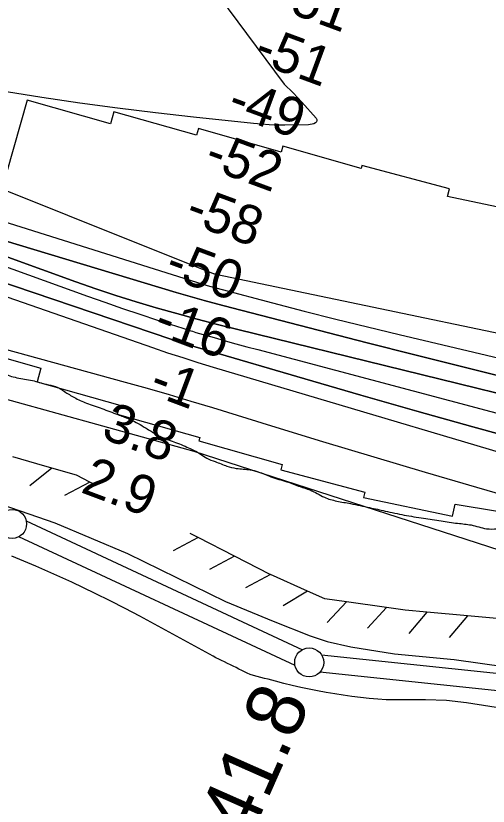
# Model space of a CAD drawing. Extents: x 3855477 to 3893699, y 299188 to 325115.
# Drawn here: x 3867708 to 3868521, y 310145 to 311507 of the extents above; entities that cross this region are included whole.
import ezdxf

# ---------------------------------------------------------------- set-up
doc = ezdxf.new("R2010")
doc.units = 0
for name, color, linetype in [('V-LEVE-TOET', 7, 'Continuous'), ('V-RIVR-EDGE', 7, 'Continuous'), ('V-RIVR-RANG', 7, 'Continuous'), ('V-RRAP-FSHR', 7, 'Continuous'), ('V-RRAP-RVMT', 7, 'Continuous'), ('V-SURV-IDEN', 7, 'Continuous'), ('V-SURV-LINE', 7, 'Continuous'), ('V-TOPO-DPTH', 7, 'Continuous'), ('V-TOPO-MAJR', 7, 'Continuous'), ('V-TOPO-MINR', 7, 'Continuous'), ('V-TOPO-WATR', 7, 'Continuous')]:
    doc.layers.add(name, color=color, linetype=linetype)

msp = doc.modelspace()

# ---------------------------------------------------------------- linework, layer by layer
at = {"layer": 'V-LEVE-TOET'}
for points in [[(3865781.2, 311251.3), (3865918.8, 311165.7), (3865932.5, 311157.1), (3865959.4, 311144.2), (3866026.4, 311126.1), (3866170, 311093.2), (3866361.4, 311047.3), (3866522.9, 311004.6), (3866745.5, 310954.1), (3866852, 310925.9), (3867039.2, 310870.9), (3867258, 310807.2), (3867465.4, 310737.1), (3867653.1, 310675), (3867775, 310633.4), (3867899.8, 310580.3), (3868068.6, 310497.4), (3868151, 310463.5), (3868214.9, 310438.2), (3868244.2, 310428.8), (3868284.9, 310419.4), (3868359.8, 310407.7)], [(3868345.9, 310328.1), (3868331.1, 310329.2), (3868316.2, 310330.6), (3868301.4, 310332.2), (3868286.5, 310334), (3868271.8, 310336), (3868257, 310338.3), (3868242.3, 310340.8), (3868227.6, 310343.5), (3868213, 310346.4), (3868198.4, 310349.5), (3868183.8, 310352.9), (3868169.4, 310356.5), (3868154.9, 310360.3), (3868148.6, 310361.9), (3868142.2, 310363.6), (3868135.9, 310365.2), (3868129.6, 310366.9), (3868123.4, 310368.6), (3868117.2, 310370.2), (3868111.1, 310371.9), (3868106.4, 310374.1), (3868101.7, 310376.5), (3868096.9, 310378.8), (3868092, 310381.2), (3868087.1, 310383.6), (3868082.2, 310386), (3868077.2, 310388.5), (3868072.2, 310390.9), (3868067.2, 310393.4), (3868062.2, 310395.8), (3868057.2, 310398.3), (3868052.2, 310400.7), (3868047.3, 310403.2), (3868022.2, 310417.3), (3867997.1, 310431.2), (3867971.9, 310445), (3867946.5, 310458.7), (3867921.2, 310472.2), (3867895.7, 310485.5), (3867870.1, 310498.7), (3867844.5, 310511.7), (3867824.2, 310521.4), (3867803.8, 310530.9), (3867783.3, 310540.3), (3867762.7, 310549.4), (3867742, 310558.4), (3867721.2, 310567.1), (3867700.4, 310575.6)], [(3868359.8, 310407.7), (3868462.9, 310397.5), (3868552.6, 310385)], [(3868553.6, 310311.9), (3868484, 310322.7), (3868449.5, 310327.2), (3868413.4, 310328), (3868381.8, 310327.9), (3868345.9, 310328.1)]]:
    msp.add_lwpolyline(points, dxfattribs=at)
at = {"layer": 'V-RIVR-EDGE'}
msp.add_spline([(3863207.1, 312832.2), (3863229.9, 312820.5), (3863243.5, 312811.8), (3863252.2, 312800.6), (3863256, 312790.4), (3863258, 312782.1), (3863257.5, 312769.5), (3863258.4, 312767), (3863259.9, 312761.2), (3863272.5, 312752), (3863294.8, 312738.3), (3863304.9, 312730.5), (3863319.5, 312720.3), (3863340.8, 312706.1), (3863352, 312701.7), (3863367, 312691), (3863378.2, 312682.7), (3863401.9, 312671), (3863427.1, 312656.4), (3863482.4, 312619.3), (3863528.5, 312589.1), (3863577.5, 312559.9), (3863604.1, 312542.3), (3863636.6, 312517.5), (3863649.7, 312508.2), (3863660.4, 312503.8), (3863682.7, 312489.7), (3863711.3, 312471.6), (3863738.9, 312455.5), (3863758.3, 312443.8), (3863780.1, 312431.2), (3863800.5, 312415.1), (3863817, 312406.8), (3863839.8, 312392.2), (3863862.1, 312377.5), (3863889.7, 312359), (3863936.7, 312330.2), (3863968.7, 312306.9), (3863983.8, 312297.1), (3864001.7, 312287.3), (3864027.4, 312273.7), (3864050.2, 312262.5), (3864086.1, 312242.9), (3864114.2, 312230.7), (3864161.8, 312206.8), (3864218.5, 312183.4), (3864252, 312168.7), (3864285.9, 312149.2), (3864306.8, 312137.5), (3864333.5, 312126.3), (3864359.7, 312113.6), (3864405.3, 312090.6), (3864433.4, 312079.9), (3864480.5, 312059.9), (3864519.8, 312042.8), (3864559.5, 312026.6), (3864597.4, 312010), (3864673.5, 311974.9), (3864716.2, 311957.3), (3864748.2, 311942.6), (3864782.2, 311928.5), (3864814.7, 311917.2), (3864837.5, 311908.4), (3864857.4, 311899.1), (3864871, 311891.8), (3864889.4, 311885.5), (3864901.6, 311881.1), (3864917.6, 311873.7), (3864943.3, 311864), (3864968, 311853.2), (3864991.3, 311844.4), (3865007.8, 311838.6), (3865027.2, 311829.8), (3865055.8, 311817.6), (3865074.3, 311810.2), (3865099.5, 311798), (3865169.3, 311767.3), (3865206.7, 311751.1), (3865252.8, 311727.2), (3865287.7, 311710.6), (3865320.2, 311696.5), (3865350.8, 311682.8), (3865409.5, 311654), (3865441.5, 311635.9), (3865468.1, 311618.4), (3865502.5, 311593.5), (3865519, 311581.9), (3865540.8, 311565.8), (3865562.2, 311550.7), (3865593.2, 311530.7), (3865614.5, 311512.7), (3865636.3, 311497.1), (3865660.6, 311479.5), (3865674.1, 311466.9), (3865694.5, 311450.8), (3865723.6, 311431.3), (3865765.8, 311405.4), (3865794.9, 311386.9), (3865822.5, 311368.4), (3865843.8, 311357.2), (3865860.8, 311347.4), (3865894.8, 311332.3), (3865922.9, 311321), (3865957.4, 311306.9), (3865987, 311294.2), (3866029.2, 311278), (3866067, 311265.3), (3866101.5, 311251.6), (3866129.6, 311241.9), (3866147.6, 311237.9), (3866169.4, 311232), (3866197.5, 311224.2), (3866231, 311213), (3866265.5, 311203.2), (3866285.9, 311197.3), (3866332, 311184.1), (3866359.1, 311172.8), (3866381, 311168.4), (3866393.6, 311165.9), (3866400.9, 311160.6), (3866406.7, 311158.6), (3866430.5, 311150.3), (3866466.4, 311139), (3866495.5, 311132.2), (3866529, 311121.9), (3866564.4, 311113.1), (3866587.2, 311105.7), (3866615.8, 311098.8), (3866658.1, 311087.1), (3866694.5, 311075.3), (3866714.4, 311068.5), (3866741.5, 311059.2), (3866767.3, 311055.7), (3866784.7, 311052.3), (3866816.3, 311042), (3866834.7, 311036.1), (3866869.2, 311024.4), (3866903.1, 311013.2), (3866908.5, 311009.3), (3866908.9, 311004.4), (3866908.9, 311002.5), (3866903.6, 311000.5), (3866900.2, 310996.6), (3866897.7, 310988.9), (3866897.7, 310988.4), (3866901.6, 310984.5), (3866906.9, 310981.1), (3866918.6, 310978.1), (3866929.8, 310976.2), (3866933.6, 310977.1), (3866939.5, 310985.4), (3866939, 310987.8), (3866937.6, 310989.8), (3866932.7, 310990.7), (3866924, 310991.7), (3866922.5, 310993.7), (3866920.6, 310999), (3866921.1, 311001.9), (3866924, 311002.9), (3866927.4, 311002.9), (3866930.8, 311002.9), (3866947.3, 310999.9), (3866980.3, 310990.6), (3867010.4, 310980.3), (3867026.4, 310974.5), (3867063.3, 310966.1), (3867093.4, 310953.4), (3867109.4, 310952.9), (3867128.8, 310946.1), (3867179.7, 310930.9), (3867221.5, 310918.2), (3867256.9, 310905.4), (3867293.3, 310893.2), (3867338.4, 310880), (3867370, 310870.7), (3867412.2, 310857.9), (3867470.9, 310839.3), (3867485.9, 310835.4), (3867499.1, 310836.9), (3867515.1, 310844.6), (3867537, 310860.6), (3867550.6, 310874.1), (3867558.4, 310888.7), (3867566.2, 310900.8), (3867575, 310909.5), (3867591, 310918.7), (3867596.9, 310919.2), (3867603.7, 310919.1), (3867628.4, 310912.3), (3867660.9, 310901), (3867685.2, 310890.8), (3867709.4, 310883.4), (3867736.1, 310878.5), (3867759.9, 310872.1), (3867775.9, 310868.2), (3867791.5, 310859.4), (3867808.4, 310849.2), (3867829.3, 310839.4), (3867856, 310830.1), (3867883.1, 310819.9), (3867902.1, 310812.5), (3867927.8, 310798.9), (3867944.7, 310788.6), (3867961.2, 310779.9), (3867986, 310770.6), (3867999.1, 310765.2), (3868011.2, 310759.8), (3868025.8, 310751.5), (3868036.4, 310744.7), (3868051, 310738.8), (3868071.4, 310731), (3868087.4, 310727.1), (3868111.6, 310724.6), (3868125.2, 310721.2), (3868147.1, 310712.4), (3868174.7, 310704.1), (3868197.5, 310695.7), (3868214.5, 310689.9), (3868239.3, 310677.2), (3868260.6, 310670.8), (3868284.4, 310666.4), (3868316.9, 310659.5), (3868344.1, 310653.6), (3868376.6, 310646.7), (3868410.1, 310641.3), (3868440.2, 310636.9), (3868468.8, 310632.4), (3868492.1, 310629.5), (3868518.4, 310623.1), (3868536.8, 310623), (3868547.5, 310623.5), (3868562.5, 310620.5), (3868581, 310615.2), (3868596.5, 310614.1), (3868609.1, 310608.8), (3868621.3, 310608.7), (3868632.9, 310606.8), (3868646, 310603.3), (3868659.6, 310598.9), (3868680.5, 310591.6), (3868698, 310586.7), (3868708.2, 310587.6), (3868719.3, 310587.6), (3868733.4, 310585.6), (3868758.2, 310579.8), (3868781.4, 310573.9), (3868804.7, 310569.9), (3868819.8, 310566), (3868824.2, 310566), (3868832.9, 310567.9), (3868838.7, 310567.9), (3868853.8, 310568.3), (3868866.9, 310566.4), (3868878.1, 310563.9), (3868891.7, 310564.4), (3868904.3, 310564.3), (3868919.8, 310562.8), (3868941.2, 310556.5), (3868965.4, 310550.6), (3869003.8, 310543.7), (3869038.3, 310539.7), (3869049.9, 310537.8), (3869068.4, 310532.4), (3869091.7, 310530.8), (3869110.6, 310529.3), (3869128.6, 310526.4), (3869142.1, 310518.6), (3869157.6, 310506.9), (3869177, 310489.8), (3869190.1, 310479.1), (3869202.2, 310469.9), (3869217.3, 310463), (3869243, 310454.7), (3869275, 310445.9), (3869293, 310441.5), (3869305.6, 310442.4), (3869320.7, 310438.5), (3869355.6, 310430.6), (3869392, 310421.3), (3869425, 310412.5), (3869458.5, 310398.8), (3869488.1, 310385.1), (3869524.9, 310367.1), (3869556, 310352), (3869578.3, 310338.8), (3869601.6, 310328.5), (3869624.4, 310322.2), (3869655.9, 310315.8), (3869691.4, 310308.9), (3869727.8, 310299.6), (3869752.5, 310295.1), (3869779.2, 310289.7), (3869816.1, 310283.3), (3869843.8, 310279.4), (3869864.6, 310274.5), (3869888.9, 310264.7), (3869906.4, 310256.9), (3869925.8, 310252.5), (3869942.3, 310244.6), (3869966, 310233.4), (3869989.3, 310228), (3870019.4, 310219.2), (3870039.3, 310217.2), (3870097.6, 310207.4), (3870123.3, 310204.9), (3870164.6, 310196.5), (3870192.7, 310192.1), (3870226.7, 310187.6), (3870265.1, 310185.1), (3870295.7, 310184), (3870321.9, 310184.9), (3870353.5, 310186.3), (3870391.3, 310183.8), (3870439.4, 310181.3), (3870483.6, 310179.7), (3870533.1, 310177.1), (3870576.3, 310177.5), (3870606, 310177.9), (3870635.1, 310178.3), (3870679.8, 310176.3), (3870709.4, 310177.7), (3870754.6, 310180), (3870836.7, 310190), (3870888.2, 310191.3), (3870912.4, 310192.7), (3870946.4, 310195.1), (3870977.5, 310199.4), (3871022.2, 310209.4), (3871049.9, 310218.6), (3871070.8, 310224.9), (3871091.7, 310224.8), (3871110.7, 310223.8), (3871127.6, 310219.9), (3871149.5, 310210.1), (3871180, 310195.9), (3871198.5, 310187.6), (3871229.5, 310178.8), (3871247, 310177.3), (3871265.9, 310176.3), (3871287.8, 310173.3), (3871310.6, 310170.8), (3871328.6, 310167.4), (3871341.2, 310165.9), (3871353.8, 310165.4), (3871367.9, 310169.3), (3871397.5, 310176), (3871415, 310178.4), (3871443.7, 310181.7), (3871467, 310183.6), (3871496.6, 310185.9), (3871534, 310188.8), (3871547.6, 310190.7), (3871571.9, 310194.5), (3871607.9, 310199.7), (3871648.2, 310206.4), (3871686.1, 310215.1), (3871735.2, 310226.1), (3871771.6, 310234.8), (3871791.1, 310234.7), (3871801.3, 310238.6), (3871824.1, 310243.4), (3871860.5, 310252), (3871894.5, 310256.3), (3871929, 310257.7), (3871967.4, 310258.6), (3872001.4, 310258), (3872037.8, 310257), (3872067.4, 310255.4), (3872101.9, 310257.8), (3872150, 310258.6), (3872177.2, 310260.5), (3872227.2, 310270.6), (3872274.4, 310278.2), (3872295.7, 310280.1), (3872312.2, 310280.1), (3872321.5, 310280), (3872332.6, 310280.5), (3872352.1, 310286.3), (3872373, 310287.2), (3872406, 310287.6), (3872422, 310288.5), (3872452.6, 310292.3), (3872488.1, 310300), (3872537.2, 310311.6), (3872583.8, 310317.8), (3872632.9, 310322.5), (3872668.8, 310329.2), (3872731, 310339.7), (3872796.1, 310351.2), (3872849.1, 310364.2), (3872896.2, 310376.7), (3872941.9, 310393.6), (3872970.6, 310407.6), (3873015.3, 310426.4), (3873066.4, 310453), (3873096, 310468.5), (3873134, 310485.4), (3873164.6, 310501.8), (3873227.8, 310533.7), (3873273, 310558.4), (3873325.6, 310585.9), (3873391.7, 310620.7), (3873435.5, 310646.9), (3873471, 310665.2), (3873502.1, 310685.1), (3873530.8, 310699.6), (3873577.9, 310719.4), (3873620.7, 310740.6), (3873650.9, 310754.6), (3873683.4, 310774.5), (3873708.3, 310795.3), (3873753, 310827.2), (3873787.6, 310858.2), (3873822.1, 310892.6), (3873850.4, 310914.4), (3873872.2, 310928.4), (3873893.7, 310947.3), (3873917, 310966.2), (3873944.3, 310988.9), (3873975.4, 311014.6), (3874011.4, 311043.2), (3874039.2, 311069.3), (3874068.9, 311102.8), (3874103, 311145.4), (3874137.6, 311188.1), (3874145.8, 311194.8), (3874157.5, 311200.2), (3874165.3, 311200.6), (3874172.6, 311200.1), (3874181.3, 311186.5), (3874183.2, 311173.9)], degree=3, dxfattribs=at)
at = {"layer": 'V-RRAP-FSHR'}
for p, q in [((3867769.5, 310727.6), (3867731.4, 310697.1)), ((3867834.9, 310703.4), (3867791.7, 310680.6)), ((3868021.8, 310607.7), (3867978.7, 310584.9)), ((3868084.1, 310575.8), (3868041, 310553)), ((3868146.4, 310543.9), (3868103.3, 310521)), ((3868210.3, 310515.3), (3868168.4, 310490.3)), ((3868277.2, 310497), (3868243.9, 310461.2)), ((3868346.5, 310487.4), (3868313.3, 310451.6)), ((3868416, 310479.5), (3868384.5, 310442.2)), ((3868485.7, 310473), (3868454.2, 310435.8))]:
    msp.add_line(p, q, dxfattribs=at)
for points in [[(3865854.4, 311447), (3867462.7, 310909.5), (3868014.1, 310756.9), (3868561.3, 310579.9), (3868891.6, 310484.2), (3869212, 310426.8), (3869707.5, 310257), (3870239.9, 310178.1), (3870574.8, 310145.5), (3871160.4, 310198.8), (3872092.5, 310231.3)], [(3867769.5, 310727.6), (3867743.9, 310735.1), (3867702.2, 310746.7)], [(3867834.9, 310703.4), (3867812.2, 310715.1), (3867769.5, 310727.6)], [(3867846.3, 310697.6), (3867834.9, 310703.4)], [(3868021.8, 310607.7), (3868008, 310614.8)], [(3868084.1, 310575.8), (3868021.8, 310607.7)], [(3868146.4, 310543.9), (3868145.7, 310544.2), (3868084.1, 310575.8)], [(3868277.2, 310497), (3868239.9, 310502.1), (3868210.3, 310515.3), (3868146.4, 310543.9)], [(3868346.5, 310487.4), (3868277.2, 310497)], [(3868416, 310479.5), (3868378.5, 310482.9), (3868346.5, 310487.4)], [(3868485.7, 310473), (3868416, 310479.5)], [(3868555.4, 310466.6), (3868485.7, 310473)]]:
    msp.add_lwpolyline(points, dxfattribs=at)
at = {"layer": 'V-RRAP-RVMT'}
for points in [[(3867727.2, 311361.7), (3867607.2, 310940.7), (3867750.8, 310899.8), (3867744.1, 310876.4), (3867886.6, 310835.8), (3867882.2, 310820.7), (3868024.6, 310780.1), (3868023, 310774.4), (3868166.5, 310733.5), (3868164.1, 310724.7), (3868308.7, 310686.1), (3868306.7, 310677.1), (3868460, 310644.8), (3868464.3, 310665.2), (3868606.7, 310641.6)], [(3868546.4, 311175.5), (3868451.4, 311195.6), (3868454.9, 311208.6), (3868303.6, 311248.9), (3868302.4, 311244.1), (3868167.7, 311282.5), (3868164.9, 311272.2), (3868022.4, 311312.8), (3868019.1, 311301.2), (3867876.7, 311341.8), (3867870.8, 311320.8), (3867727.2, 311361.7)]]:
    msp.add_lwpolyline(points, dxfattribs=at)
at = {"layer": 'V-SURV-LINE'}
for points in [[(3867725.5, 310636.5), (3868201.3, 310414.6)], [(3868188.6, 310387.5), (3867712.9, 310609.3)], [(3868234.5, 310405.5), (3868765.5, 310350.1)], [(3868762.3, 310320.3), (3868231.3, 310375.6)]]:
    msp.add_lwpolyline(points, dxfattribs=at)
for centre in [(3867701.1, 310631.3), (3868213, 310392.6)]:
    msp.add_circle(centre, 25, dxfattribs=at)
at = {"layer": 'V-TOPO-DPTH'}
for points in [[(3866374.7, 311745.5), (3867192, 311336.9), (3867225.6, 311320.7), (3867259.5, 311305.1), (3867293.8, 311290.5), (3867328.4, 311276.6), (3867372, 311259.7), (3867428.8, 311238.4), (3867485.8, 311217.8), (3867543.3, 311198.3), (3867601, 311179.5), (3868018.9, 311048), (3868030, 311044.6), (3868041, 311041.3), (3868052.1, 311038.2), (3868063.3, 311035.1), (3868149.8, 311012.4), (3868204.3, 310998.3), (3868258.9, 310984.4), (3868313.5, 310970.9), (3868368.2, 310957.7), (3868744.4, 310868.5)], [(3866374.7, 311745.5), (3867192, 311336.9), (3867225.6, 311320.7), (3867259.5, 311305.1), (3867293.8, 311290.5), (3867328.4, 311276.6), (3867372, 311259.7), (3867428.8, 311238.4), (3867485.8, 311217.8), (3867543.3, 311198.3), (3867601, 311179.5), (3868018.9, 311048), (3868030, 311044.6), (3868041, 311041.3), (3868052.1, 311038.2), (3868063.3, 311035.1), (3868149.8, 311012.4), (3868204.3, 310998.3), (3868258.9, 310984.4), (3868313.5, 310970.9), (3868368.2, 310957.7), (3868744.4, 310868.5)], [(3868660.7, 310826.3), (3868090.3, 310966.3), (3868055, 310975.2), (3868019.8, 310984.3), (3867984.7, 310993.8), (3867949.6, 311003.6), (3867914.7, 311014), (3867880, 311024.8), (3867845.5, 311036.4), (3867811.2, 311048.4), (3867264.2, 311246.6), (3867251.9, 311251.2), (3867239.6, 311256), (3867227.4, 311261), (3867215.3, 311266.1), (3866252.8, 311686.1)], [(3866252.8, 311686.1), (3867215.3, 311266.1), (3867227.4, 311261), (3867239.6, 311256), (3867251.9, 311251.2), (3867264.2, 311246.6), (3867811.2, 311048.4), (3867845.5, 311036.4), (3867880, 311024.8), (3867914.7, 311014), (3867949.6, 311003.6), (3867984.7, 310993.8), (3868019.8, 310984.3), (3868055, 310975.2), (3868090.3, 310966.3), (3868660.7, 310826.3)], [(3868560.5, 310881.6), (3868477.8, 310902), (3868395.3, 310922.7), (3868312.8, 310943.7), (3868079.9, 311003.6), (3868055.8, 311010), (3868031.8, 311016.5), (3868007.8, 311023.3), (3867984, 311030.4), (3867657.9, 311128.5), (3867588.4, 311150.1), (3867519.1, 311172.4), (3867450.2, 311195.9), (3867381.6, 311220.1), (3867255.3, 311265.9), (3867250, 311267.9), (3867244.8, 311269.9), (3867239.6, 311272.1), (3867234.5, 311274.3), (3867048.9, 311356.9), (3866951.2, 311400.8), (3866853.6, 311445.1), (3866756.4, 311490.2)], [(3868560.5, 310881.6), (3868477.8, 310902), (3868395.3, 310922.7), (3868312.8, 310943.7), (3868079.9, 311003.6), (3868055.8, 311010), (3868031.8, 311016.5), (3868007.8, 311023.3), (3867984, 311030.4), (3867657.9, 311128.5), (3867588.4, 311150.1), (3867519.1, 311172.4), (3867450.2, 311195.9), (3867381.6, 311220.1), (3867255.3, 311265.9), (3867250, 311267.9), (3867244.8, 311269.9), (3867239.6, 311272.1), (3867234.5, 311274.3), (3867048.9, 311356.9), (3866951.2, 311400.8), (3866853.6, 311445.1), (3866756.4, 311490.2)], [(3867670.9, 311052.4), (3867974.4, 310950), (3867988.9, 310945.2), (3868003.5, 310940.5), (3868018.1, 310936), (3868032.8, 310931.7), (3868205.5, 310881.2), (3868301.8, 310853.3), (3868398.3, 310825.8), (3868494.9, 310798.9), (3868591.6, 310772.3)], [(3868591.6, 310772.3), (3868494.9, 310798.9), (3868398.3, 310825.8), (3868301.8, 310853.3), (3868205.5, 310881.2), (3868032.8, 310931.7), (3868018.1, 310936), (3868003.5, 310940.5), (3867988.9, 310945.2), (3867974.4, 310950), (3867670.9, 311052.4)], [(3867411.3, 311009), (3867896.2, 310875.6), (3867933.8, 310865.1), (3867971.5, 310854.3), (3868009, 310843.2), (3868046.4, 310831.8), (3868148, 310800.5), (3868236.2, 310773.6), (3868324.5, 310746.9), (3868412.9, 310720.6), (3868501.5, 310694.6), (3868698.6, 310637.2)]]:
    msp.add_lwpolyline(points, dxfattribs=at)
at = {"layer": 'V-TOPO-MAJR'}
for points in [[(3867945.5, 311691.8), (3868170, 311389.5), (3868185.3, 311374.1), (3868200.2, 311358.3), (3868224.9, 311330.8), (3868226, 311328.5), (3868226.2, 311326.4), (3868225.4, 311324.4), (3868223.7, 311322.6), (3868220.9, 311321.2), (3868218, 311320.1), (3868214.9, 311319.5), (3868211.8, 311319.2), (3868171.3, 311318.7), (3868157.8, 311318.8), (3868144.3, 311319.2), (3868130.8, 311320.1), (3868117.3, 311321.3), (3868013.4, 311332.3), (3867948.1, 311339.7), (3867882.8, 311347.8), (3867817.6, 311356.7), (3867752.6, 311366.4), (3867676.4, 311378.2)], [(3867291.2, 311365.7), (3868047.7, 311063.1), (3868048.1, 311062.9), (3868049.7, 311062.5), (3868051.7, 311062.1), (3868052.1, 311062), (3868838.5, 310897.5)]]:
    msp.add_lwpolyline(points, dxfattribs=at)
at = {"layer": 'V-TOPO-MINR'}
for points in [[(3866374.7, 311745.5), (3867192, 311336.9), (3867225.6, 311320.7), (3867259.5, 311305.1), (3867293.8, 311290.5), (3867328.4, 311276.6), (3867372, 311259.7), (3867428.8, 311238.4), (3867485.8, 311217.8), (3867543.3, 311198.3), (3867601, 311179.5), (3868018.9, 311048), (3868030, 311044.6), (3868041, 311041.3), (3868052.1, 311038.2), (3868063.3, 311035.1), (3868149.8, 311012.4), (3868204.3, 310998.3), (3868258.9, 310984.4), (3868313.5, 310970.9), (3868368.2, 310957.7), (3868744.4, 310868.5)], [(3866252.8, 311686.1), (3867215.3, 311266.1), (3867227.4, 311261), (3867239.6, 311256), (3867251.9, 311251.2), (3867264.2, 311246.6), (3867811.2, 311048.4), (3867845.5, 311036.4), (3867880, 311024.8), (3867914.7, 311014), (3867949.6, 311003.6), (3867984.7, 310993.8), (3868019.8, 310984.3), (3868055, 310975.2), (3868090.3, 310966.3), (3868660.7, 310826.3)], [(3866756.4, 311490.2), (3866853.6, 311445.1), (3866951.2, 311400.8), (3867048.9, 311356.9), (3867234.5, 311274.3), (3867239.6, 311272.1), (3867244.8, 311269.9), (3867250, 311267.9), (3867255.3, 311265.9), (3867381.6, 311220.1), (3867450.2, 311195.9), (3867519.1, 311172.4), (3867588.4, 311150.1), (3867657.9, 311128.5), (3867984, 311030.4), (3868007.8, 311023.3), (3868031.8, 311016.5), (3868055.8, 311010), (3868079.9, 311003.6), (3868312.8, 310943.7), (3868395.3, 310922.7), (3868477.8, 310902), (3868560.5, 310881.6)], [(3866737.1, 311429), (3866861.7, 311383.2), (3866985.9, 311336), (3867192.9, 311255.3), (3867213.2, 311247.5), (3867233.5, 311239.8), (3867253.9, 311232.2), (3867274.3, 311224.8), (3867831.1, 311024), (3867861.1, 311013.4), (3867891.1, 311002.9), (3867921.3, 310992.8), (3867951.5, 310982.8), (3868006.1, 310965.1), (3868009.1, 310964.2), (3868012, 310963.3), (3868014.9, 310962.4), (3868017.9, 310961.5), (3868049.4, 310952.4), (3868068.1, 310947.1), (3868086.9, 310941.9), (3868105.7, 310936.7), (3868124.5, 310931.7), (3868722.2, 310773.1)], [(3867258.9, 311173.2), (3867942.8, 310935.4), (3867968.9, 310926.5), (3867995.1, 310917.9), (3868021.3, 310909.6), (3868047.7, 310901.6), (3868739.6, 310695.8)], [(3867670.9, 311052.4), (3867974.4, 310950), (3867988.9, 310945.2), (3868003.5, 310940.5), (3868018.1, 310936), (3868032.8, 310931.7), (3868205.5, 310881.2), (3868301.8, 310853.3), (3868398.3, 310825.8), (3868494.9, 310798.9), (3868591.6, 310772.3)]]:
    msp.add_lwpolyline(points, dxfattribs=at)
at = {"layer": 'V-TOPO-WATR'}
msp.add_lwpolyline([(3867411.3, 311009), (3867896.2, 310875.6), (3867933.8, 310865.1), (3867971.5, 310854.3), (3868009, 310843.2), (3868046.4, 310831.8), (3868148, 310800.5), (3868236.2, 310773.6), (3868324.5, 310746.9), (3868412.9, 310720.6), (3868501.5, 310694.6), (3868698.6, 310637.2)], dxfattribs=at)

# ---------------------------------------------------------------- texts
at = {"layer": 'V-RIVR-RANG'}
for s, rotation, p in [('-51', 339.7168, (3868149.5, 311522.8)), ('-51', 339.7168, (3868114.6, 311429.1)), ('-49', 339.7168, (3868068.9, 311339.4)), ('-52', 339.7168, (3868029.3, 311247.5)), ('-58', 339.7168, (3867996.3, 311153)), ('-50', 339.7168, (3867961.2, 311059.4)), ('-16', 339.4383, (3867941.8, 310960.3)), ('-1', 339.4383, (3867934.4, 310856.3)), ('3.8', 339.4383, (3867852.5, 310780.2)), ('2.9', 339.4383, (3867817.4, 310686.5))]:
    msp.add_text(s, height=67, rotation=rotation, dxfattribs=at).set_placement(p)
at = {"layer": 'V-SURV-IDEN'}
for s, rotation, p in [('1153+41.8', 66.1394, (3867958.8, 309742.9)), ('1159+15.7', 51.9106, (3868410.2, 309733.7))]:
    msp.add_text(s, height=100, rotation=rotation, dxfattribs=at).set_placement(p)

doc.saveas('drawing.dxf')
